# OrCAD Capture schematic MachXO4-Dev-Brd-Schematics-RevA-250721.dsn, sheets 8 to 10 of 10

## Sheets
8 Analog Sense and Control: size B
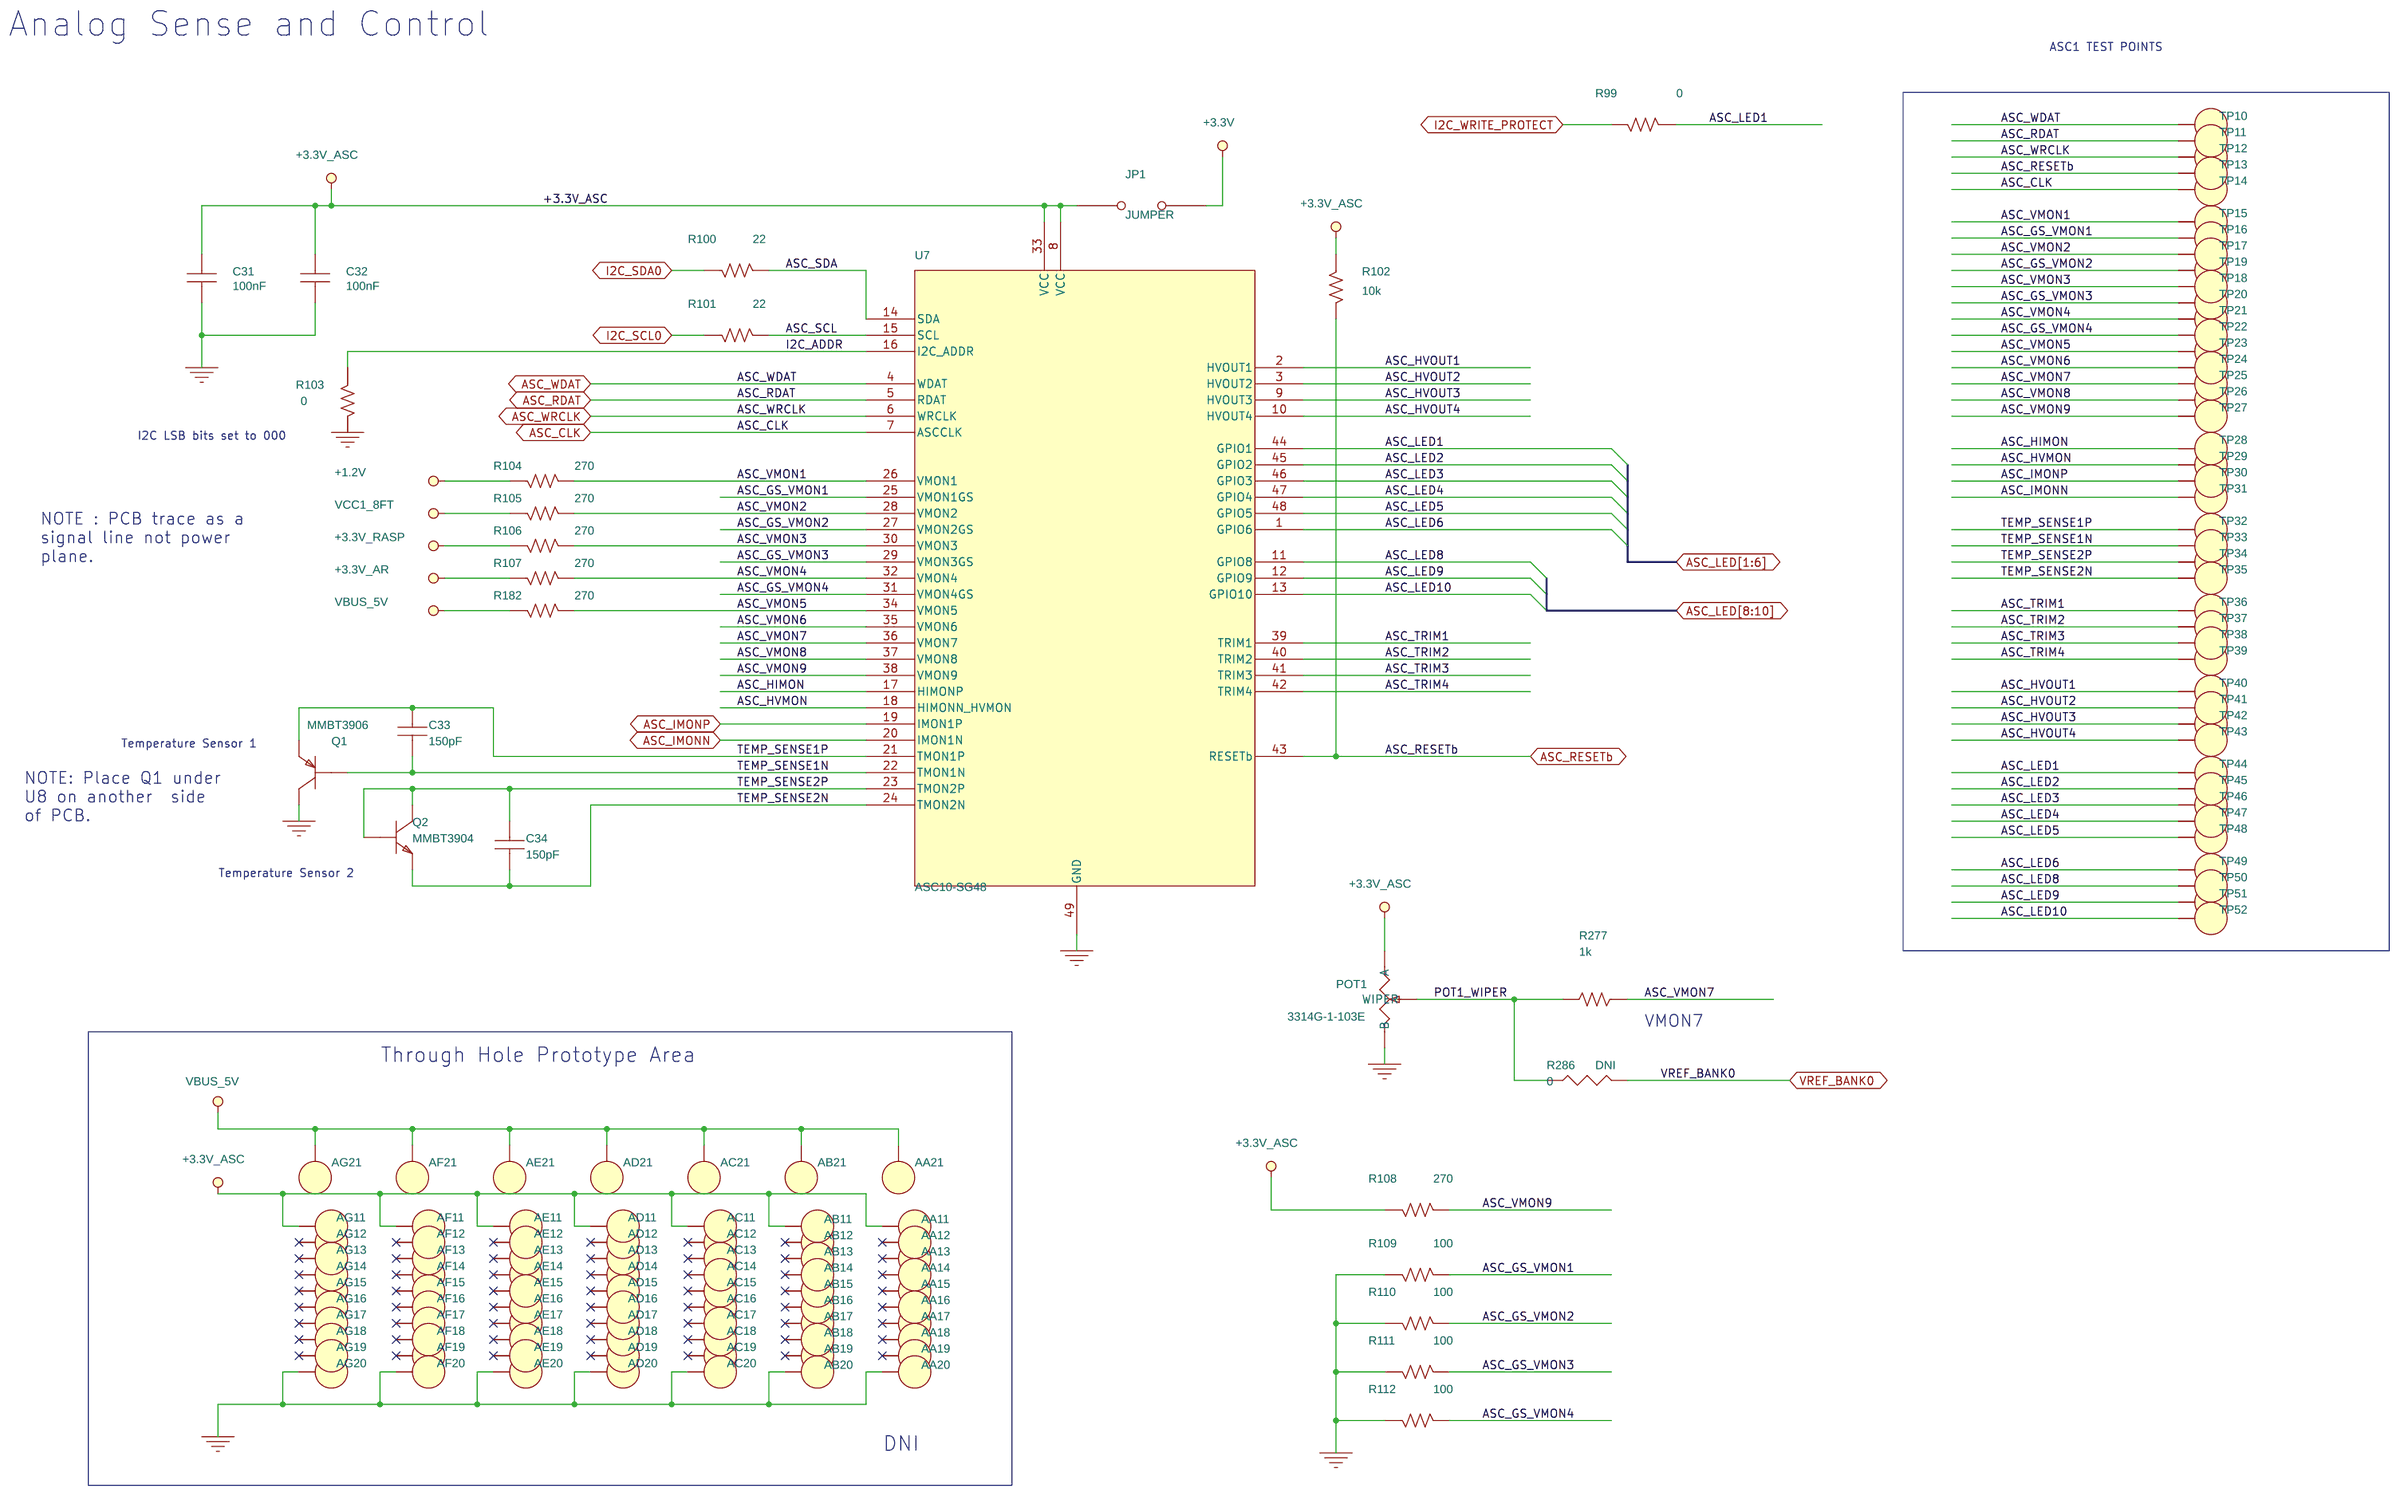
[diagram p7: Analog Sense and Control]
9 POWER DECOUPLING AND LED'S: size B
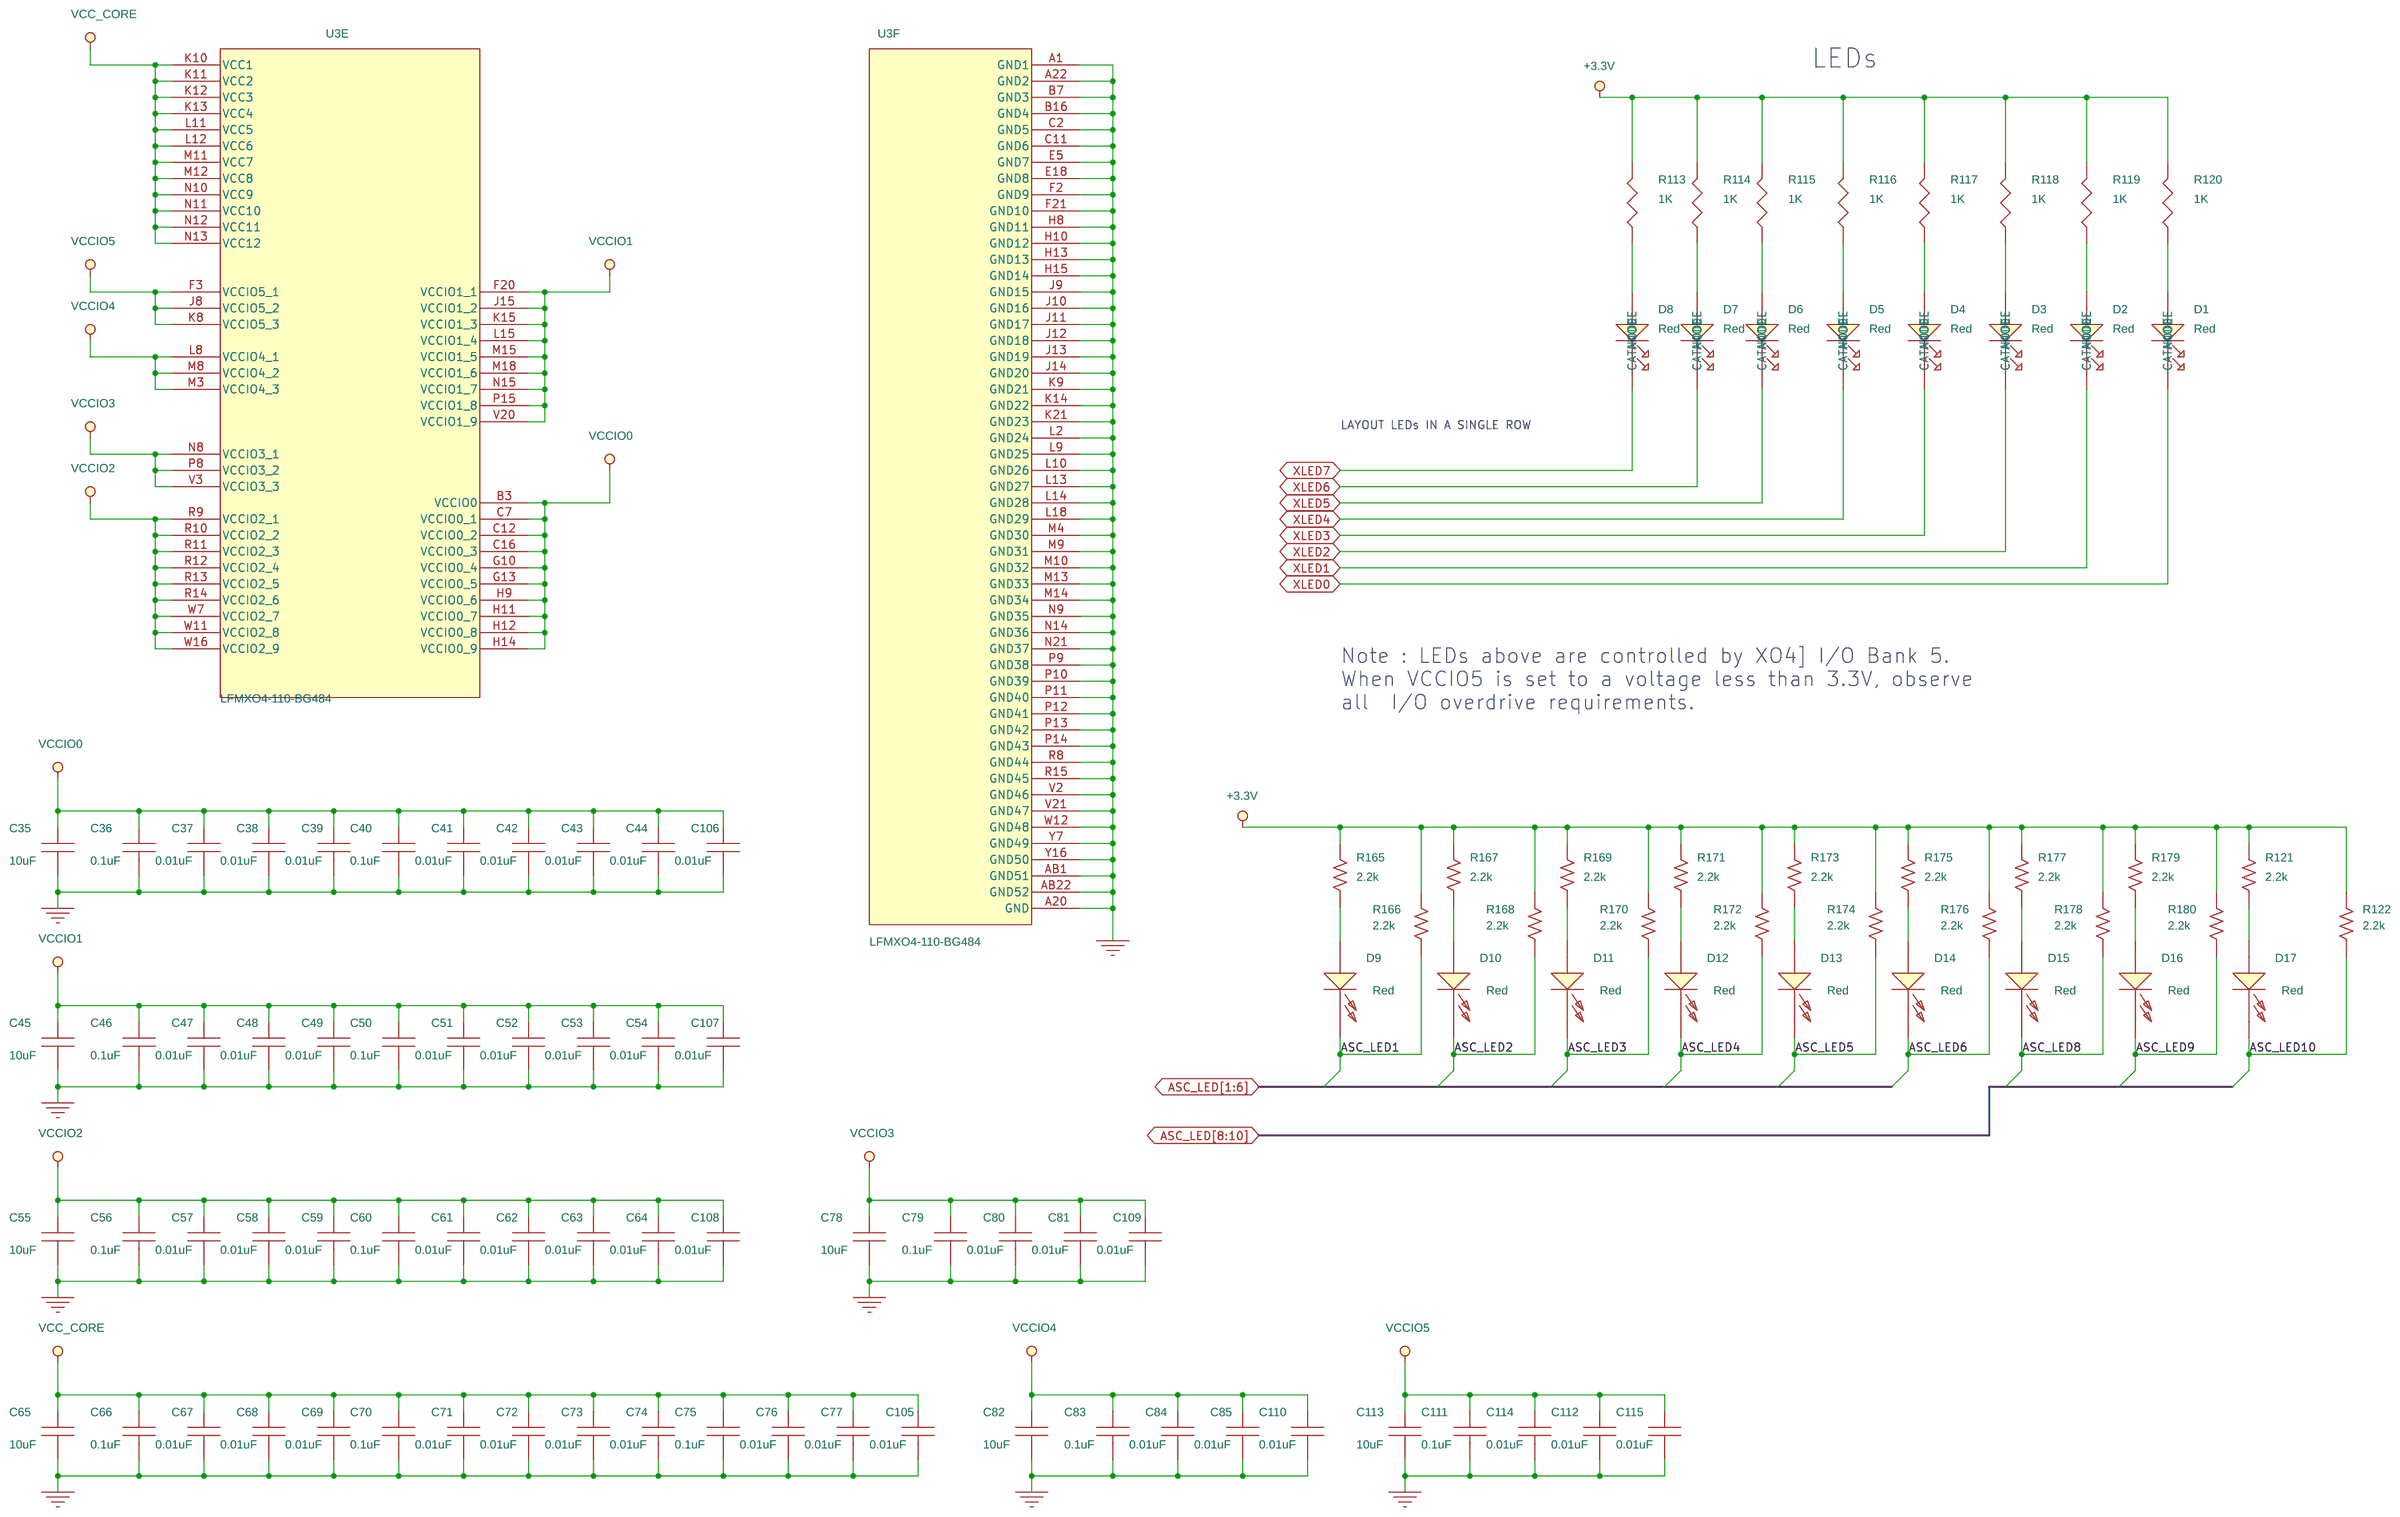
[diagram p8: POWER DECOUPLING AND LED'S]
10 POWER REGULATORS: size B
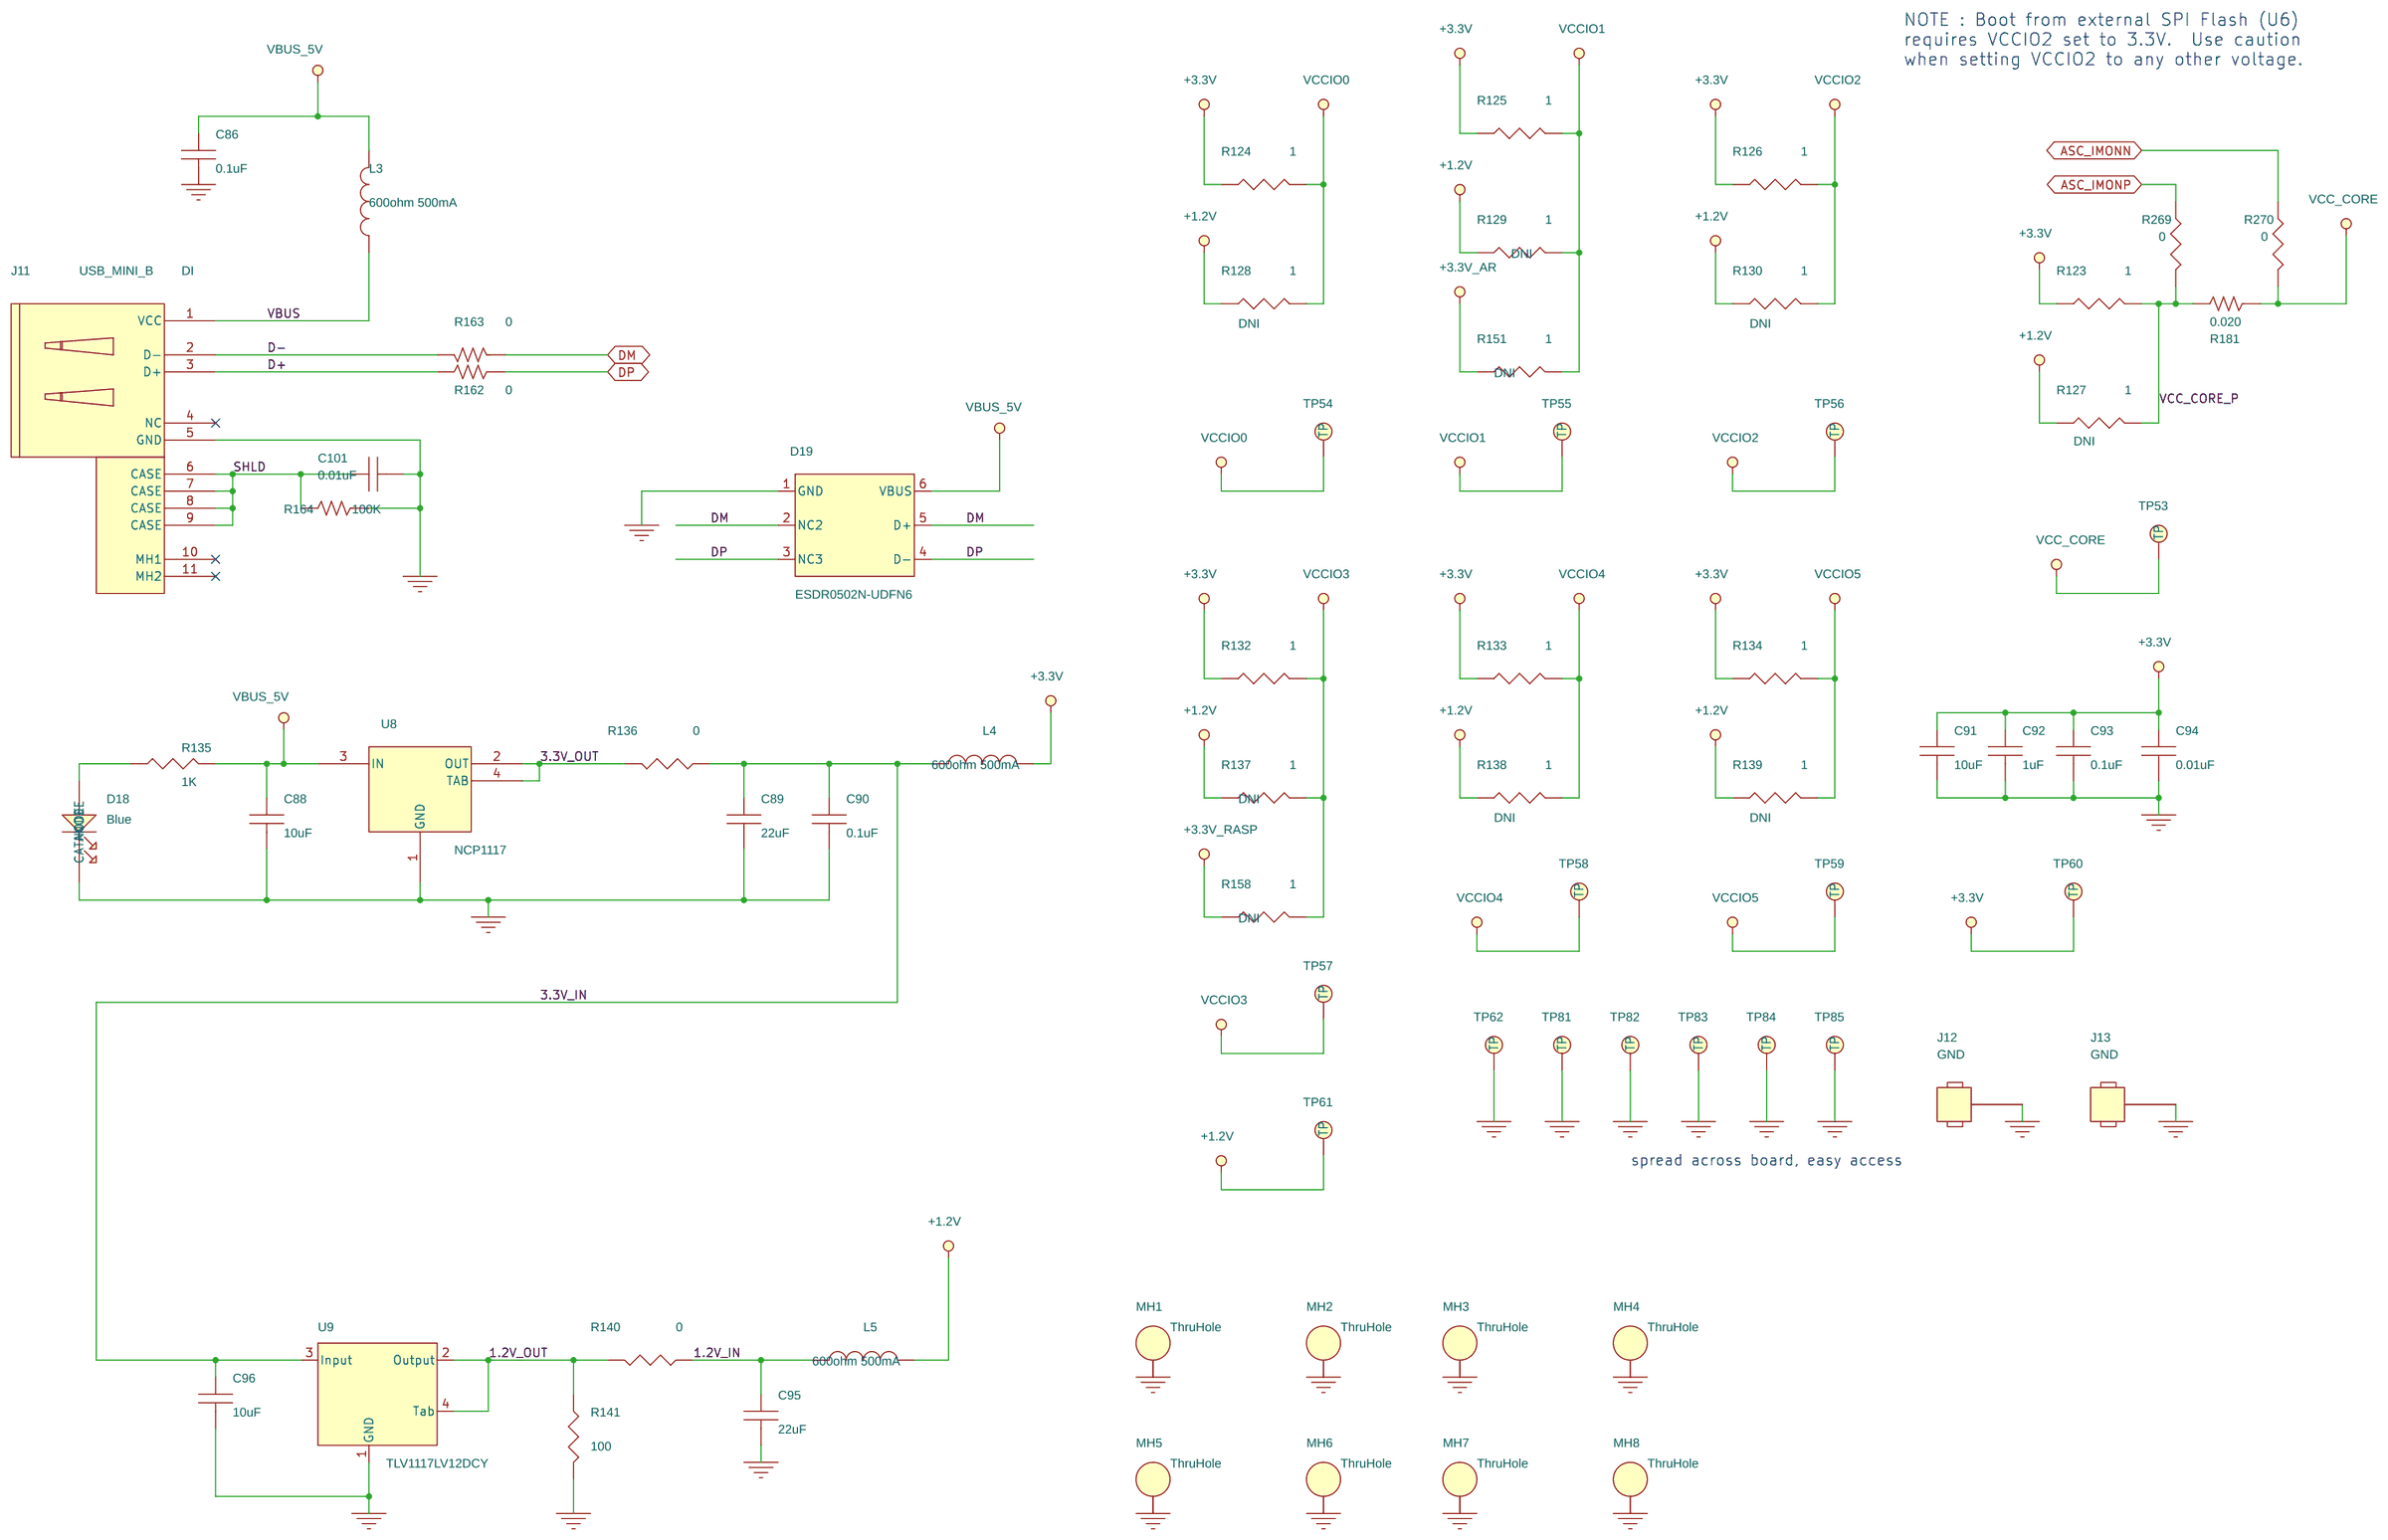
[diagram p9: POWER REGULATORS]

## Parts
sheet Analog Sense and Control
AA11  T POINT R  [TP]
AA12  T POINT R  [TP]
AA13  T POINT R  [TP]
AA14  T POINT R  [TP]
AA15  T POINT R  [TP]
AA16  T POINT R  [TP]
AA17  T POINT R  [TP]
AA18  T POINT R  [TP]
AA19  T POINT R  [TP]
AA20  T POINT R  [TP]
AA21  T POINT R  [TP]
AB11  T POINT R  [TP]
AB12  T POINT R  [TP]
AB13  T POINT R  [TP]
AB14  T POINT R  [TP]
AB15  T POINT R  [TP]
AB16  T POINT R  [TP]
AB17  T POINT R  [TP]
AB18  T POINT R  [TP]
AB19  T POINT R  [TP]
AB20  T POINT R  [TP]
AB21  T POINT R  [TP]
AC11  T POINT R  [TP]
AC12  T POINT R  [TP]
AC13  T POINT R  [TP]
AC14  T POINT R  [TP]
AC15  T POINT R  [TP]
AC16  T POINT R  [TP]
AC17  T POINT R  [TP]
AC18  T POINT R  [TP]
AC19  T POINT R  [TP]
AC20  T POINT R  [TP]
AC21  T POINT R  [TP]
AD11  T POINT R  [TP]
AD12  T POINT R  [TP]
AD13  T POINT R  [TP]
AD14  T POINT R  [TP]
AD15  T POINT R  [TP]
AD16  T POINT R  [TP]
AD17  T POINT R  [TP]
AD18  T POINT R  [TP]
AD19  T POINT R  [TP]
AD20  T POINT R  [TP]
AD21  T POINT R  [TP]
AE11  T POINT R  [TP]
AE12  T POINT R  [TP]
AE13  T POINT R  [TP]
AE14  T POINT R  [TP]
AE15  T POINT R  [TP]
AE16  T POINT R  [TP]
AE17  T POINT R  [TP]
AE18  T POINT R  [TP]
AE19  T POINT R  [TP]
AE20  T POINT R  [TP]
AE21  T POINT R  [TP]
AF11  T POINT R  [TP]
AF12  T POINT R  [TP]
AF13  T POINT R  [TP]
AF14  T POINT R  [TP]
AF15  T POINT R  [TP]
AF16  T POINT R  [TP]
AF17  T POINT R  [TP]
AF18  T POINT R  [TP]
AF19  T POINT R  [TP]
AF20  T POINT R  [TP]
AF21  T POINT R  [TP]
AG11  T POINT R  [TP]
AG12  T POINT R  [TP]
AG13  T POINT R  [TP]
AG14  T POINT R  [TP]
AG15  T POINT R  [TP]
AG16  T POINT R  [TP]
AG17  T POINT R  [TP]
AG18  T POINT R  [TP]
AG19  T POINT R  [TP]
AG20  T POINT R  [TP]
AG21  T POINT R  [TP]
C31  100nF  [C0603]
C32  100nF  [C0603]
C33  150pF  [C0603]
C34  150pF  [C0603]
JP1  JUMPER  [Header_1x2]
POT1  3314G-1-103E  [sot23-3314G-1]
Q1  MMBT3906  [MMBT3906]
Q2  MMBT3904  [MMBT3904]
R99  0  [R0603]
R100  22  [R0603]
R101  22  [R0603]
R102  10k  [R0603]
R103  0  [R0603]
R104  270  [R0603]
R105  270  [R0603]
R106  270  [R0603]
R107  270  [R0603]
R108  270  [R0603]
R109  100  [R0603]
R110  100  [R0603]
R111  100  [R0603]
R112  100  [R0603]
R182  270  [R0603]
R277  1k  [R0603]
R286  0  [R0603]
TP10  T POINT R  [TP]
TP11  T POINT R  [TP]
TP12  T POINT R  [TP]
TP13  T POINT R  [TP]
TP14  T POINT R  [TP]
TP15  T POINT R  [TP]
TP16  T POINT R  [TP]
TP17  T POINT R  [TP]
TP18  T POINT R  [TP]
TP19  T POINT R  [TP]
TP20  T POINT R  [TP]
TP21  T POINT R  [TP]
TP22  T POINT R  [TP]
TP23  T POINT R  [TP]
TP24  T POINT R  [TP]
TP25  T POINT R  [TP]
TP26  T POINT R  [TP]
TP27  T POINT R  [TP]
TP28  T POINT R  [TP]
TP29  T POINT R  [TP]
TP30  T POINT R  [TP]
TP31  T POINT R  [TP]
TP32  T POINT R  [TP]
TP33  T POINT R  [TP]
TP34  T POINT R  [TP]
TP35  T POINT R  [TP]
TP36  T POINT R  [TP]
TP37  T POINT R  [TP]
TP38  T POINT R  [TP]
TP39  T POINT R  [TP]
TP40  T POINT R  [TP]
TP41  T POINT R  [TP]
TP42  T POINT R  [TP]
TP43  T POINT R  [TP]
TP44  T POINT R  [TP]
TP45  T POINT R  [TP]
TP46  T POINT R  [TP]
TP47  T POINT R  [TP]
TP48  T POINT R  [TP]
TP49  T POINT R  [TP]
TP50  T POINT R  [TP]
TP51  T POINT R  [TP]
TP52  T POINT R  [TP]
U7  ASC10-SG48  [TQFN_48]
sheet POWER DECOUPLING AND LED'S
C35  10uF  [C0603]
C36  0.1uF  [C0201]
C37  0.01uF  [C0201]
C38  0.01uF  [C0201]
C39  0.01uF  [C0201]
C40  0.1uF  [C0201]
C41  0.01uF  [C0201]
C42  0.01uF  [C0201]
C43  0.01uF  [C0201]
C44  0.01uF  [C0201]
C45  10uF  [C0603]
C46  0.1uF  [C0201]
C47  0.01uF  [C0201]
C48  0.01uF  [C0201]
C49  0.01uF  [C0201]
C50  0.1uF  [C0201]
C51  0.01uF  [C0201]
C52  0.01uF  [C0201]
C53  0.01uF  [C0201]
C54  0.01uF  [C0201]
C55  10uF  [C0603]
C56  0.1uF  [C0201]
C57  0.01uF  [C0201]
C58  0.01uF  [C0201]
C59  0.01uF  [C0201]
C60  0.1uF  [C0201]
C61  0.01uF  [C0201]
C62  0.01uF  [C0201]
C63  0.01uF  [C0201]
C64  0.01uF  [C0201]
C65  10uF  [C0603]
C66  0.1uF  [C0201]
C67  0.01uF  [C0201]
C68  0.01uF  [C0201]
C69  0.01uF  [C0201]
C70  0.1uF  [C0201]
C71  0.01uF  [C0201]
C72  0.01uF  [C0201]
C73  0.01uF  [C0201]
C74  0.01uF  [C0201]
C75  0.1uF  [C0201]
C76  0.01uF  [C0201]
C77  0.01uF  [C0201]
C78  10uF  [C0603]
C79  0.1uF  [C0201]
C80  0.01uF  [C0201]
C81  0.01uF  [C0201]
C82  10uF  [C0603]
C83  0.1uF  [C0201]
C84  0.01uF  [C0201]
C85  0.01uF  [C0201]
C105  0.01uF  [C0201]
C106  0.01uF  [C0201]
C107  0.01uF  [C0201]
C108  0.01uF  [C0201]
C109  0.01uF  [C0201]
C110  0.01uF  [C0201]
C111  0.1uF  [C0201]
C112  0.01uF  [C0201]
C113  10uF  [C0603]
C114  0.01uF  [C0201]
C115  0.01uF  [C0201]
D1  Red  [led_0603]
D2  Red  [led_0603]
D3  Red  [led_0603]
D4  Red  [led_0603]
D5  Red  [led_0603]
D6  Red  [led_0603]
D7  Red  [led_0603]
D8  Red  [led_0603]
D9  Red  [led_0603]
D10  Red  [led_0603]
D11  Red  [led_0603]
D12  Red  [led_0603]
D13  Red  [led_0603]
D14  Red  [led_0603]
D15  Red  [led_0603]
D16  Red  [led_0603]
D17  Red  [led_0603]
R113  1K  [R0603]
R114  1K  [R0603]
R115  1K  [R0603]
R116  1K  [R0603]
R117  1K  [R0603]
R118  1K  [R0603]
R119  1K  [R0603]
R120  1K  [R0603]
R121  2.2k  [R0603]
R122  2.2k  [R0603]
R165  2.2k  [R0603]
R166  2.2k  [R0603]
R167  2.2k  [R0603]
R168  2.2k  [R0603]
R169  2.2k  [R0603]
R170  2.2k  [R0603]
R171  2.2k  [R0603]
R172  2.2k  [R0603]
R173  2.2k  [R0603]
R174  2.2k  [R0603]
R175  2.2k  [R0603]
R176  2.2k  [R0603]
R177  2.2k  [R0603]
R178  2.2k  [R0603]
R179  2.2k  [R0603]
R180  2.2k  [R0603]
U3  LFMXO4-110-BG484  [BGA484-080]  (sections A,B,C,D,E,F,G)
sheet POWER REGULATORS
C86  0.1uF  [C0402]
C88  10uF  [C0603]
C89  22uF  [cc0805]
C90  0.1uF  [C0402]
C91  10uF  [C0603]
C92  1uF  [C0402]
C93  0.1uF  [C0402]
C94  0.01uF  [C0402]
C95  22uF  [cc0805]
C96  10uF  [C0603]
C101  0.01uF  [C0402]
D18  Blue  [led_0603]
D19  ESDR0502N-UDFN6  [UDFN6_040]
J11  USB_MINI_B  [usb2-0-rec-240-0001-9]
J12  GND  [TUR_TH]
J13  GND  [TUR_TH]
L3  600ohm 500mA  [fb0603]
L4  600ohm 500mA  [fb0603]
L5  600ohm 500mA  [fb0603]
MH1  ThruHole  [MTG125]
MH2  ThruHole  [MTG125]
MH3  ThruHole  [MTG125]
MH4  ThruHole  [MTG125]
MH5  ThruHole  [MTG125]
MH6  ThruHole  [MTG125]
MH7  ThruHole  [MTG125]
MH8  ThruHole  [MTG125]
R123  1  [R0603]
R124  1  [R0603]
R125  1  [R0603]
R126  1  [R0603]
R127  1  [R0603]
R128  1  [R0603]
R129  1  [R0603]
R130  1  [R0603]
R132  1  [R0603]
R133  1  [R0603]
R134  1  [R0603]
R135  1K  [R0603]
R136  0  [R0603]
R137  1  [R0603]
R138  1  [R0603]
R139  1  [R0603]
R140  0  [R0603]
R141  100  [R0603]
R151  1  [R0603]
R158  1  [R0603]
R162  0  [R0402]
R163  0  [R0402]
R164  100K  [R0603]
R181  0.020  [SM_R_1206]
R269  0  [R0603]
R270  0  [R0603]
TP53  TP_S_40_63  [TP]
TP54  TP_S_40_63  [TP]
TP55  TP_S_40_63  [TP]
TP56  TP_S_40_63  [TP]
TP57  TP_S_40_63  [TP]
TP58  TP_S_40_63  [TP]
TP59  TP_S_40_63  [TP]
TP60  TP_S_40_63  [TP]
TP61  TP_S_40_63  [TP]
TP62  TP_S_40_63  [TP]
TP81  TP_S_40_63  [TP]
TP82  TP_S_40_63  [TP]
TP83  TP_S_40_63  [TP]
TP84  TP_S_40_63  [TP]
TP85  TP_S_40_63  [TP]
U8  NCP1117  [sot223_4p]
U9  TLV1117LV12DCY  [sot223_4p]

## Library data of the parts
AA11 AA21 = T_POINT_R_0: Assy: DNI; COMPFIXED: NO; COMPGROUP: 0; COMPHEIGHT: 0.000; COMPKEY: NO; COMPLOC: [100.000,3800.000]; COMPLOCKED: NO; COMPROT: 0; COMPSIDE: TOP; DECOUPLER: NO; MEMORY: NO
AA12 = T_POINT_R_0: Assy: DNI; COMPFIXED: NO; COMPGROUP: 0; COMPHEIGHT: 0.000; COMPKEY: NO; COMPLOC: [100.000,3700.000]; COMPLOCKED: NO; COMPROT: 0; COMPSIDE: TOP; DECOUPLER: NO; MEMORY: NO
AA13 = T_POINT_R_0: Assy: DNI; COMPFIXED: NO; COMPGROUP: 0; COMPHEIGHT: 0.000; COMPKEY: NO; COMPLOC: [100.000,3600.000]; COMPLOCKED: NO; COMPROT: 0; COMPSIDE: TOP; DECOUPLER: NO; MEMORY: NO
AA14 = T_POINT_R_0: Assy: DNI; COMPFIXED: NO; COMPGROUP: 0; COMPHEIGHT: 0.000; COMPKEY: NO; COMPLOC: [100.000,3500.000]; COMPLOCKED: NO; COMPROT: 0; COMPSIDE: TOP; DECOUPLER: NO; MEMORY: NO
AA15 = T_POINT_R_0: Assy: DNI; COMPFIXED: NO; COMPGROUP: 0; COMPHEIGHT: 0.000; COMPKEY: NO; COMPLOC: [100.000,3400.000]; COMPLOCKED: NO; COMPROT: 0; COMPSIDE: TOP; DECOUPLER: NO; MEMORY: NO
AA16 = T_POINT_R_0: Assy: DNI; COMPFIXED: NO; COMPGROUP: 0; COMPHEIGHT: 0.000; COMPKEY: NO; COMPLOC: [100.000,3300.000]; COMPLOCKED: NO; COMPROT: 0; COMPSIDE: TOP; DECOUPLER: NO; MEMORY: NO
AA17 = T_POINT_R_0: Assy: DNI; COMPFIXED: NO; COMPGROUP: 0; COMPHEIGHT: 0.000; COMPKEY: NO; COMPLOC: [100.000,3200.000]; COMPLOCKED: NO; COMPROT: 0; COMPSIDE: TOP; DECOUPLER: NO; MEMORY: NO
AA18 = T_POINT_R_0: Assy: DNI; COMPFIXED: NO; COMPGROUP: 0; COMPHEIGHT: 0.000; COMPKEY: NO; COMPLOC: [100.000,3100.000]; COMPLOCKED: NO; COMPROT: 0; COMPSIDE: TOP; DECOUPLER: NO; MEMORY: NO
AA19 = T_POINT_R_0: Assy: DNI; COMPFIXED: NO; COMPGROUP: 0; COMPHEIGHT: 0.000; COMPKEY: NO; COMPLOC: [100.000,3000.000]; COMPLOCKED: NO; COMPROT: 0; COMPSIDE: TOP; DECOUPLER: NO; MEMORY: NO
AA20 = T_POINT_R_0: Assy: DNI; COMPFIXED: NO; COMPGROUP: 0; COMPHEIGHT: 0.000; COMPKEY: NO; COMPLOC: [100.000,2900.000]; COMPLOCKED: NO; COMPROT: 0; COMPSIDE: TOP; DECOUPLER: NO; MEMORY: NO
AB11 AB21 = T_POINT_R_0: Assy: DNI; COMPFIXED: NO; COMPGROUP: 0; COMPHEIGHT: 0.000; COMPKEY: NO; COMPLOC: [200.000,3800.000]; COMPLOCKED: NO; COMPROT: 0; COMPSIDE: TOP; DECOUPLER: NO; MEMORY: NO
AB12 = T_POINT_R_0: Assy: DNI; COMPFIXED: NO; COMPGROUP: 0; COMPHEIGHT: 0.000; COMPKEY: NO; COMPLOC: [200.000,3700.000]; COMPLOCKED: NO; COMPROT: 0; COMPSIDE: TOP; DECOUPLER: NO; MEMORY: NO
AB13 = T_POINT_R_0: Assy: DNI; COMPFIXED: NO; COMPGROUP: 0; COMPHEIGHT: 0.000; COMPKEY: NO; COMPLOC: [200.000,3600.000]; COMPLOCKED: NO; COMPROT: 0; COMPSIDE: TOP; DECOUPLER: NO; MEMORY: NO
AB14 = T_POINT_R_0: Assy: DNI; COMPFIXED: NO; COMPGROUP: 0; COMPHEIGHT: 0.000; COMPKEY: NO; COMPLOC: [200.000,3500.000]; COMPLOCKED: NO; COMPROT: 0; COMPSIDE: TOP; DECOUPLER: NO; MEMORY: NO
AB15 = T_POINT_R_0: Assy: DNI; COMPFIXED: NO; COMPGROUP: 0; COMPHEIGHT: 0.000; COMPKEY: NO; COMPLOC: [200.000,3400.000]; COMPLOCKED: NO; COMPROT: 0; COMPSIDE: TOP; DECOUPLER: NO; MEMORY: NO
AB16 = T_POINT_R_0: Assy: DNI; COMPFIXED: NO; COMPGROUP: 0; COMPHEIGHT: 0.000; COMPKEY: NO; COMPLOC: [200.000,3300.000]; COMPLOCKED: NO; COMPROT: 0; COMPSIDE: TOP; DECOUPLER: NO; MEMORY: NO
AB17 = T_POINT_R_0: Assy: DNI; COMPFIXED: NO; COMPGROUP: 0; COMPHEIGHT: 0.000; COMPKEY: NO; COMPLOC: [200.000,3200.000]; COMPLOCKED: NO; COMPROT: 0; COMPSIDE: TOP; DECOUPLER: NO; MEMORY: NO
AB18 = T_POINT_R_0: Assy: DNI; COMPFIXED: NO; COMPGROUP: 0; COMPHEIGHT: 0.000; COMPKEY: NO; COMPLOC: [200.000,3100.000]; COMPLOCKED: NO; COMPROT: 0; COMPSIDE: TOP; DECOUPLER: NO; MEMORY: NO
AB19 = T_POINT_R_0: Assy: DNI; COMPFIXED: NO; COMPGROUP: 0; COMPHEIGHT: 0.000; COMPKEY: NO; COMPLOC: [200.000,3000.000]; COMPLOCKED: NO; COMPROT: 0; COMPSIDE: TOP; DECOUPLER: NO; MEMORY: NO
AB20 = T_POINT_R_0: Assy: DNI; COMPFIXED: NO; COMPGROUP: 0; COMPHEIGHT: 0.000; COMPKEY: NO; COMPLOC: [200.000,2900.000]; COMPLOCKED: NO; COMPROT: 0; COMPSIDE: TOP; DECOUPLER: NO; MEMORY: NO
AC11 AC21 = T_POINT_R_0: Assy: DNI; COMPFIXED: NO; COMPGROUP: 0; COMPHEIGHT: 0.000; COMPKEY: NO; COMPLOC: [300.000,3800.000]; COMPLOCKED: NO; COMPROT: 0; COMPSIDE: TOP; DECOUPLER: NO; MEMORY: NO
AC12 = T_POINT_R_0: Assy: DNI; COMPFIXED: NO; COMPGROUP: 0; COMPHEIGHT: 0.000; COMPKEY: NO; COMPLOC: [300.000,3700.000]; COMPLOCKED: NO; COMPROT: 0; COMPSIDE: TOP; DECOUPLER: NO; MEMORY: NO
AC13 = T_POINT_R_0: Assy: DNI; COMPFIXED: NO; COMPGROUP: 0; COMPHEIGHT: 0.000; COMPKEY: NO; COMPLOC: [300.000,3600.000]; COMPLOCKED: NO; COMPROT: 0; COMPSIDE: TOP; DECOUPLER: NO; MEMORY: NO
AC14 = T_POINT_R_0: Assy: DNI; COMPFIXED: NO; COMPGROUP: 0; COMPHEIGHT: 0.000; COMPKEY: NO; COMPLOC: [300.000,3500.000]; COMPLOCKED: NO; COMPROT: 0; COMPSIDE: TOP; DECOUPLER: NO; MEMORY: NO
AC15 = T_POINT_R_0: Assy: DNI; COMPFIXED: NO; COMPGROUP: 0; COMPHEIGHT: 0.000; COMPKEY: NO; COMPLOC: [300.000,3400.000]; COMPLOCKED: NO; COMPROT: 0; COMPSIDE: TOP; DECOUPLER: NO; MEMORY: NO
AC16 = T_POINT_R_0: Assy: DNI; COMPFIXED: NO; COMPGROUP: 0; COMPHEIGHT: 0.000; COMPKEY: NO; COMPLOC: [300.000,3300.000]; COMPLOCKED: NO; COMPROT: 0; COMPSIDE: TOP; DECOUPLER: NO; MEMORY: NO
AC17 = T_POINT_R_0: Assy: DNI; COMPFIXED: NO; COMPGROUP: 0; COMPHEIGHT: 0.000; COMPKEY: NO; COMPLOC: [300.000,3200.000]; COMPLOCKED: NO; COMPROT: 0; COMPSIDE: TOP; DECOUPLER: NO; MEMORY: NO
AC18 = T_POINT_R_0: Assy: DNI; COMPFIXED: NO; COMPGROUP: 0; COMPHEIGHT: 0.000; COMPKEY: NO; COMPLOC: [300.000,3100.000]; COMPLOCKED: NO; COMPROT: 0; COMPSIDE: TOP; DECOUPLER: NO; MEMORY: NO
AC19 = T_POINT_R_0: Assy: DNI; COMPFIXED: NO; COMPGROUP: 0; COMPHEIGHT: 0.000; COMPKEY: NO; COMPLOC: [300.000,3000.000]; COMPLOCKED: NO; COMPROT: 0; COMPSIDE: TOP; DECOUPLER: NO; MEMORY: NO
AC20 = T_POINT_R_0: Assy: DNI; COMPFIXED: NO; COMPGROUP: 0; COMPHEIGHT: 0.000; COMPKEY: NO; COMPLOC: [300.000,2900.000]; COMPLOCKED: NO; COMPROT: 0; COMPSIDE: TOP; DECOUPLER: NO; MEMORY: NO
AD11 AD21 = T_POINT_R_0: Assy: DNI; COMPFIXED: NO; COMPGROUP: 0; COMPHEIGHT: 0.000; COMPKEY: NO; COMPLOC: [400.000,3800.000]; COMPLOCKED: NO; COMPROT: 0; COMPSIDE: TOP; DECOUPLER: NO; MEMORY: NO
AD12 = T_POINT_R_0: Assy: DNI; COMPFIXED: NO; COMPGROUP: 0; COMPHEIGHT: 0.000; COMPKEY: NO; COMPLOC: [400.000,3700.000]; COMPLOCKED: NO; COMPROT: 0; COMPSIDE: TOP; DECOUPLER: NO; MEMORY: NO
AD13 = T_POINT_R_0: Assy: DNI; COMPFIXED: NO; COMPGROUP: 0; COMPHEIGHT: 0.000; COMPKEY: NO; COMPLOC: [400.000,3600.000]; COMPLOCKED: NO; COMPROT: 0; COMPSIDE: TOP; DECOUPLER: NO; MEMORY: NO
AD14 = T_POINT_R_0: Assy: DNI; COMPFIXED: NO; COMPGROUP: 0; COMPHEIGHT: 0.000; COMPKEY: NO; COMPLOC: [400.000,3500.000]; COMPLOCKED: NO; COMPROT: 0; COMPSIDE: TOP; DECOUPLER: NO; MEMORY: NO
AD15 = T_POINT_R_0: Assy: DNI; COMPFIXED: NO; COMPGROUP: 0; COMPHEIGHT: 0.000; COMPKEY: NO; COMPLOC: [400.000,3400.000]; COMPLOCKED: NO; COMPROT: 0; COMPSIDE: TOP; DECOUPLER: NO; MEMORY: NO
AD16 = T_POINT_R_0: Assy: DNI; COMPFIXED: NO; COMPGROUP: 0; COMPHEIGHT: 0.000; COMPKEY: NO; COMPLOC: [400.000,3300.000]; COMPLOCKED: NO; COMPROT: 0; COMPSIDE: TOP; DECOUPLER: NO; MEMORY: NO
AD17 = T_POINT_R_0: Assy: DNI; COMPFIXED: NO; COMPGROUP: 0; COMPHEIGHT: 0.000; COMPKEY: NO; COMPLOC: [400.000,3200.000]; COMPLOCKED: NO; COMPROT: 0; COMPSIDE: TOP; DECOUPLER: NO; MEMORY: NO
AD18 = T_POINT_R_0: Assy: DNI; COMPFIXED: NO; COMPGROUP: 0; COMPHEIGHT: 0.000; COMPKEY: NO; COMPLOC: [400.000,3100.000]; COMPLOCKED: NO; COMPROT: 0; COMPSIDE: TOP; DECOUPLER: NO; MEMORY: NO
AD19 = T_POINT_R_0: Assy: DNI; COMPFIXED: NO; COMPGROUP: 0; COMPHEIGHT: 0.000; COMPKEY: NO; COMPLOC: [400.000,3000.000]; COMPLOCKED: NO; COMPROT: 0; COMPSIDE: TOP; DECOUPLER: NO; MEMORY: NO
AD20 = T_POINT_R_0: Assy: DNI; COMPFIXED: NO; COMPGROUP: 0; COMPHEIGHT: 0.000; COMPKEY: NO; COMPLOC: [400.000,2900.000]; COMPLOCKED: NO; COMPROT: 0; COMPSIDE: TOP; DECOUPLER: NO; MEMORY: NO
AE11 AE21 = T_POINT_R_0: Assy: DNI; COMPFIXED: NO; COMPGROUP: 0; COMPHEIGHT: 0.000; COMPKEY: NO; COMPLOC: [500.000,3800.000]; COMPLOCKED: NO; COMPROT: 0; COMPSIDE: TOP; DECOUPLER: NO; MEMORY: NO
AE12 = T_POINT_R_0: Assy: DNI; COMPFIXED: NO; COMPGROUP: 0; COMPHEIGHT: 0.000; COMPKEY: NO; COMPLOC: [500.000,3700.000]; COMPLOCKED: NO; COMPROT: 0; COMPSIDE: TOP; DECOUPLER: NO; MEMORY: NO
AE13 = T_POINT_R_0: Assy: DNI; COMPFIXED: NO; COMPGROUP: 0; COMPHEIGHT: 0.000; COMPKEY: NO; COMPLOC: [500.000,3600.000]; COMPLOCKED: NO; COMPROT: 0; COMPSIDE: TOP; DECOUPLER: NO; MEMORY: NO
AE14 = T_POINT_R_0: Assy: DNI; COMPFIXED: NO; COMPGROUP: 0; COMPHEIGHT: 0.000; COMPKEY: NO; COMPLOC: [500.000,3500.000]; COMPLOCKED: NO; COMPROT: 0; COMPSIDE: TOP; DECOUPLER: NO; MEMORY: NO
AE15 = T_POINT_R_0: Assy: DNI; COMPFIXED: NO; COMPGROUP: 0; COMPHEIGHT: 0.000; COMPKEY: NO; COMPLOC: [500.000,3400.000]; COMPLOCKED: NO; COMPROT: 0; COMPSIDE: TOP; DECOUPLER: NO; MEMORY: NO
AE16 = T_POINT_R_0: Assy: DNI; COMPFIXED: NO; COMPGROUP: 0; COMPHEIGHT: 0.000; COMPKEY: NO; COMPLOC: [500.000,3300.000]; COMPLOCKED: NO; COMPROT: 0; COMPSIDE: TOP; DECOUPLER: NO; MEMORY: NO
AE17 = T_POINT_R_0: Assy: DNI; COMPFIXED: NO; COMPGROUP: 0; COMPHEIGHT: 0.000; COMPKEY: NO; COMPLOC: [500.000,3200.000]; COMPLOCKED: NO; COMPROT: 0; COMPSIDE: TOP; DECOUPLER: NO; MEMORY: NO
AE18 = T_POINT_R_0: Assy: DNI; COMPFIXED: NO; COMPGROUP: 0; COMPHEIGHT: 0.000; COMPKEY: NO; COMPLOC: [500.000,3100.000]; COMPLOCKED: NO; COMPROT: 0; COMPSIDE: TOP; DECOUPLER: NO; MEMORY: NO
AE19 = T_POINT_R_0: Assy: DNI; COMPFIXED: NO; COMPGROUP: 0; COMPHEIGHT: 0.000; COMPKEY: NO; COMPLOC: [500.000,3000.000]; COMPLOCKED: NO; COMPROT: 0; COMPSIDE: TOP; DECOUPLER: NO; MEMORY: NO
AE20 = T_POINT_R_0: Assy: DNI; COMPFIXED: NO; COMPGROUP: 0; COMPHEIGHT: 0.000; COMPKEY: NO; COMPLOC: [500.000,2900.000]; COMPLOCKED: NO; COMPROT: 0; COMPSIDE: TOP; DECOUPLER: NO; MEMORY: NO
AF11 AF21 = T_POINT_R_0: Assy: DNI; COMPFIXED: NO; COMPGROUP: 0; COMPHEIGHT: 0.000; COMPKEY: NO; COMPLOC: [600.000,3800.000]; COMPLOCKED: NO; COMPROT: 0; COMPSIDE: TOP; DECOUPLER: NO; MEMORY: NO
AF12 = T_POINT_R_0: Assy: DNI; COMPFIXED: NO; COMPGROUP: 0; COMPHEIGHT: 0.000; COMPKEY: NO; COMPLOC: [600.000,3700.000]; COMPLOCKED: NO; COMPROT: 0; COMPSIDE: TOP; DECOUPLER: NO; MEMORY: NO
AF13 = T_POINT_R_0: Assy: DNI; COMPFIXED: NO; COMPGROUP: 0; COMPHEIGHT: 0.000; COMPKEY: NO; COMPLOC: [600.000,3600.000]; COMPLOCKED: NO; COMPROT: 0; COMPSIDE: TOP; DECOUPLER: NO; MEMORY: NO
AF14 = T_POINT_R_0: Assy: DNI; COMPFIXED: NO; COMPGROUP: 0; COMPHEIGHT: 0.000; COMPKEY: NO; COMPLOC: [600.000,3500.000]; COMPLOCKED: NO; COMPROT: 0; COMPSIDE: TOP; DECOUPLER: NO; MEMORY: NO
AF15 = T_POINT_R_0: Assy: DNI; COMPFIXED: NO; COMPGROUP: 0; COMPHEIGHT: 0.000; COMPKEY: NO; COMPLOC: [600.000,3400.000]; COMPLOCKED: NO; COMPROT: 0; COMPSIDE: TOP; DECOUPLER: NO; MEMORY: NO
AF16 = T_POINT_R_0: Assy: DNI; COMPFIXED: NO; COMPGROUP: 0; COMPHEIGHT: 0.000; COMPKEY: NO; COMPLOC: [600.000,3300.000]; COMPLOCKED: NO; COMPROT: 0; COMPSIDE: TOP; DECOUPLER: NO; MEMORY: NO
AF17 = T_POINT_R_0: Assy: DNI; COMPFIXED: NO; COMPGROUP: 0; COMPHEIGHT: 0.000; COMPKEY: NO; COMPLOC: [600.000,3200.000]; COMPLOCKED: NO; COMPROT: 0; COMPSIDE: TOP; DECOUPLER: NO; MEMORY: NO
AF18 = T_POINT_R_0: Assy: DNI; COMPFIXED: NO; COMPGROUP: 0; COMPHEIGHT: 0.000; COMPKEY: NO; COMPLOC: [600.000,3100.000]; COMPLOCKED: NO; COMPROT: 0; COMPSIDE: TOP; DECOUPLER: NO; MEMORY: NO
AF19 = T_POINT_R_0: Assy: DNI; COMPFIXED: NO; COMPGROUP: 0; COMPHEIGHT: 0.000; COMPKEY: NO; COMPLOC: [600.000,3000.000]; COMPLOCKED: NO; COMPROT: 0; COMPSIDE: TOP; DECOUPLER: NO; MEMORY: NO
AF20 = T_POINT_R_0: Assy: DNI; COMPFIXED: NO; COMPGROUP: 0; COMPHEIGHT: 0.000; COMPKEY: NO; COMPLOC: [600.000,2900.000]; COMPLOCKED: NO; COMPROT: 0; COMPSIDE: TOP; DECOUPLER: NO; MEMORY: NO
AG11 = T_POINT_R_0: Assy: DNI; COMPFIXED: NO; COMPGROUP: 0; COMPHEIGHT: 0.000; COMPKEY: NO; COMPLOC: [700.000,3100.000]; COMPLOCKED: NO; COMPROT: 0; COMPSIDE: TOP; DECOUPLER: NO; MEMORY: NO
AG12 = T_POINT_R_0: Assy: DNI; COMPFIXED: NO; COMPGROUP: 0; COMPHEIGHT: 0.000; COMPKEY: NO; COMPLOC: [700.000,3400.000]; COMPLOCKED: NO; COMPROT: 0; COMPSIDE: TOP; DECOUPLER: NO; MEMORY: NO
AG13 = T_POINT_R_0: Assy: DNI; COMPFIXED: NO; COMPGROUP: 0; COMPHEIGHT: 0.000; COMPKEY: NO; COMPLOC: [700.000,3300.000]; COMPLOCKED: NO; COMPROT: 0; COMPSIDE: TOP; DECOUPLER: NO; MEMORY: NO
AG14 = T_POINT_R_0: Assy: DNI; COMPFIXED: NO; COMPGROUP: 0; COMPHEIGHT: 0.000; COMPKEY: NO; COMPLOC: [700.000,3200.000]; COMPLOCKED: NO; COMPROT: 0; COMPSIDE: TOP; DECOUPLER: NO; MEMORY: NO
AG15 = T_POINT_R_0: Assy: DNI; COMPFIXED: NO; COMPGROUP: 0; COMPHEIGHT: 0.000; COMPKEY: NO; COMPLOC: [700.000,3000.000]; COMPLOCKED: NO; COMPROT: 0; COMPSIDE: TOP; DECOUPLER: NO; MEMORY: NO
AG16 = T_POINT_R_0: Assy: DNI; COMPFIXED: NO; COMPGROUP: 0; COMPHEIGHT: 0.000; COMPKEY: NO; COMPLOC: [700.000,2900.000]; COMPLOCKED: NO; COMPROT: 0; COMPSIDE: TOP; DECOUPLER: NO; MEMORY: NO
AG17 AG21 = T_POINT_R_0: Assy: DNI; COMPFIXED: NO; COMPGROUP: 0; COMPHEIGHT: 0.000; COMPKEY: NO; COMPLOC: [700.000,3800.000]; COMPLOCKED: NO; COMPROT: 0; COMPSIDE: TOP; DECOUPLER: NO; MEMORY: NO
AG18 = T_POINT_R_0: Assy: DNI; COMPFIXED: NO; COMPGROUP: 0; COMPHEIGHT: 0.000; COMPKEY: NO; COMPLOC: [700.000,3600.000]; COMPLOCKED: NO; COMPROT: 0; COMPSIDE: TOP; DECOUPLER: NO; MEMORY: NO
AG19 = T_POINT_R_0: Assy: DNI; COMPFIXED: NO; COMPGROUP: 0; COMPHEIGHT: 0.000; COMPKEY: NO; COMPLOC: [700.000,3700.000]; COMPLOCKED: NO; COMPROT: 0; COMPSIDE: TOP; DECOUPLER: NO; MEMORY: NO
AG20 = T_POINT_R_0: Assy: DNI; COMPFIXED: NO; COMPGROUP: 0; COMPHEIGHT: 0.000; COMPKEY: NO; COMPLOC: [700.000,3500.000]; COMPLOCKED: NO; COMPROT: 0; COMPSIDE: TOP; DECOUPLER: NO; MEMORY: NO
C31-C34 = CAP_NP: COMPFIXED: NO; COMPGROUP: 0; COMPHEIGHT: 0.000; COMPKEY: NO; COMPLOC: [2185.000,2685.000]; COMPLOCKED: NO; COMPROT: 90; COMPSIDE: TOP; DECOUPLER: NO; FPLIST: SM/C_0805; MEMORY: NO; populate: DI
JP1 = JUMPER_0
POT1 = POT_SM_2: COMPFIXED: NO; COMPGROUP: 0; COMPHEIGHT: 0.000; COMPKEY: NO; COMPLOC: [2340.000,1325.000]; COMPLOCKED: NO; COMPROT: 90; COMPSIDE: TOP; DECOUPLER: NO; FPLIST: TH/SLIDEPOT/4/25MM; MEMORY: NO; Populate: DI
Q1 = 2N3906_1
Q2 = 2N3904_0
R99 = R: RES 0.0 OHM 1/10W JUMP 0603 SMD; COMPFIXED: NO; COMPHEIGHT: 0.000; COMPKEY: NO; COMPLOC: [3325.000,1400.000]; COMPLOCKED: NO; COMPROT: 180; COMPSIDE: TOP; DECOUPLER: NO; FPLIST: AX/RC05; MEMORY: NO; Populate: DI
R100 R101 R104-R112 R182 = R: COMPFIXED: NO; COMPGROUP: 0; COMPHEIGHT: 0.000; COMPKEY: NO; COMPLOC: [950.000,2200.000]; COMPLOCKED: NO; COMPROT: 0; COMPSIDE: BOT; DECOUPLER: NO; MEMORY: NO; Populate: DI
R102 = R: RES 10K OHM 1/10W 5% 0603; COMPFIXED: NO; COMPGROUP: 0; COMPHEIGHT: 0.000; COMPKEY: NO; COMPLOC: [950.000,2200.000]; COMPLOCKED: NO; COMPROT: 0; COMPSIDE: BOT; DECOUPLER: NO; MEMORY: NO; Populate: DI
R103 = R: RES 0.0 OHM 1/10W JUMP 0603 SMD; COMPFIXED: NO; COMPHEIGHT: 0.000; COMPKEY: NO; COMPLOC: [2340.000,1470.000]; COMPLOCKED: NO; COMPSIDE: BOT; DECOUPLER: NO; MEMORY: NO; Populate: DI
R277 = R: RES 1K OHM 1/10W 1% 0603 SMD; COMPFIXED: NO; COMPGROUP: 0; COMPHEIGHT: 0.000; COMPKEY: NO; COMPLOC: [2340.000,1470.000]; COMPLOCKED: NO; COMPROT: 0; COMPSIDE: BOT; DECOUPLER: NO; MEMORY: NO; Populate: DI
R286 = RES_0: Assy: DNI
TP10-TP52 = T_POINT_R_0: COMPFIXED: NO; COMPGROUP: 0; COMPHEIGHT: 0.000; COMPKEY: NO; COMPLOC: [200.000,3200.000]; COMPLOCKED: NO; COMPROT: 0; COMPSIDE: TOP; DECOUPLER: NO; MEMORY: NO
U7 = ASC1013-48QFN_8
C35 C45 C55 C65 C78 C82 C113 = 10uF_0603
C36 C40 C46 C50 C56 C60 C66 C70 C75 C79 C83 C111 = 0u1_0402: CAP CER 0.1UF 16V 10% X5R 0201; Manufacturer: TDK; Manufacturer Part Number: C0603X5R1C104K030BC
C37-C39 C41-C44 C47-C49 C51-C54 C57-C59 C61-C64 C67-C69 C71-C74 C76 C77 C80 C81 C84 C85 C105-C110 C112 C114 C115 = 0_01uF_0402: CAP CER 10000PF 16V 10% X7R 0201; Manufacturer: Yageo; Manufacturer Part Number: CC0201KRX7R7BB103
D1-D8 = LED_0603_Red
D9 D13 = LN1251C: COMPFIXED: NO; COMPGROUP: 0; COMPHEIGHT: 0.000; COMPKEY: NO; COMPLOC: [2950.000,1925.000]; COMPLOCKED: NO; COMPROT: 0; COMPSIDE: TOP; DECOUPLER: NO; MEMORY: NO
D10 D14 = LN1251C: COMPFIXED: NO; COMPGROUP: 0; COMPHEIGHT: 0.000; COMPKEY: NO; COMPLOC: [2950.000,2000.000]; COMPLOCKED: NO; COMPROT: 0; COMPSIDE: TOP; DECOUPLER: NO; MEMORY: NO
D11 D15 D17 = LN1251C: COMPFIXED: NO; COMPGROUP: 0; COMPHEIGHT: 0.000; COMPKEY: NO; COMPLOC: [2950.000,2075.000]; COMPLOCKED: NO; COMPROT: 0; COMPSIDE: TOP; DECOUPLER: NO; MEMORY: NO
D12 D16 = LN1251C: COMPFIXED: NO; COMPGROUP: 0; COMPHEIGHT: 0.000; COMPKEY: NO; COMPLOC: [2950.000,2150.000]; COMPLOCKED: NO; COMPROT: 0; COMPSIDE: TOP; DECOUPLER: NO; MEMORY: NO
R113-R120 R135 = 1k_0402: RES 1K OHM 1/10W 1% 0603 SMD; Digikey P/N: 311-1.00KHRCT-ND; Manufacturer Part Number: RC0603FR-071KL
R121 R122 R165-R180 = R: COMPFIXED: NO; COMPGROUP: 0; COMPHEIGHT: 0.000; COMPKEY: NO; COMPLOC: [2786.250,4509.367]; COMPLOCKED: NO; COMPROT: 0; COMPSIDE: BOT; DECOUPLER: NO; MEMORY: NO; Populate: DI
U3 = LFMXO4-110-BG484
C86 C90 C93 = 0u1_0402: CAP CER 0.1UF 16V 10% X7R 0402
C88 C91 C96 = 10uF_0603: CAP CER 10UF 10V 20% X5R 0603
C89 C95 = 22uF_0805: CAP CER 22UF 10V 20% X5R 0805
C92 = 1uF_0402: CAP CER 1UF 6.3V 10% X5R 0402
C94 C101 = 0_01uF_0402: CAP CER 10000PF 16V 5% X7R 0402
D18 = LED_0603_Green: LED 468NM BLUE CLEAR 0603 SMD; Digikey P/N: 160-1646-1-ND; Manufacturer Part Number: LTST-C190TBKT
D19 = ESDR0502
J11 = USB_MINI_B_0: COMPFIXED: NO; COMPGROUP: 0; COMPHEIGHT: 0.000; COMPKEY: NO; COMPLOC: [370.000,2590.000]; COMPLOCKED: NO; COMPROT: 270; COMPSIDE: TOP; DECOUPLER: NO; FPLIST: TYPE_B; MEMORY: NO; Populate: DI
J12 J13 = HEADER_1: BOM1_Sensor_Population: POPULATE; BOM2_DUT_Population: DNP; Man. Part #: 1573-2; Manufacturer: Keystone Electronics
L3-L5 = FB0603: FERRITE CHIP 600 OHM 500MA 0603
MH1-MH8 = T_POINT_R_0
R123-R126 R132-R134 = 1R_0.25W_0603: Manufacturer: Vishay
R127-R130 R137-R139 R151 R158 = 1R_0.25W_0603: ASSY: DNI; Manufacturer: Vishay
R136 R140 R269 R270 = 0R_0603: RES 0.0 OHM 1/10W JUMP 0603 SMD
R141 = 100R_0603
R162 R163 = R: COMPFIXED: NO; COMPHEIGHT: 0.000; COMPKEY: NO; COMPLOC: [970.000,1160.000]; COMPLOCKED: NO; COMPROT: 180; COMPSIDE: TOP; DECOUPLER: NO; FPLIST: SM/R_0603; MEMORY: NO; Populate: DI
R164 = R: COMPFIXED: NO; COMPGROUP: 0; COMPHEIGHT: 0.000; COMPKEY: NO; COMPLOC: [970.000,1160.000]; COMPLOCKED: NO; COMPROT: 180; COMPSIDE: TOP; DECOUPLER: NO; FPLIST: SM/R_0603; MEMORY: NO; Populate: DI
R181 = R: COMPFIXED: NO; COMPGROUP: 0; COMPHEIGHT: 0.000; COMPKEY: NO; COMPLOC: [3325.000,1400.000]; COMPLOCKED: NO; COMPROT: 180; COMPSIDE: TOP; DECOUPLER: NO; FPLIST: AX/RC05; MEMORY: NO; Populate: DI
TP53-TP62 TP81-TP85 = TP_S_40_63: Assy: DNI
U8 = NCP1117: IC REG LDO 3.3V 1A SOT223
U9 = FAN1112: IC REG LDO 1.2V 1A SOT223-3; Digikey P/N: 296-28776-1-ND; Manufacturer: TI

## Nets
1.2V_IN: C95.1 L5.2 R140.1
1.2V_OUT: R140.2 R141.1 U9.2(Output) U9.4(Tab)
3.3V_IN: C89.1 C90.1 C96.1 L4.2 R136.1 U9.3(Input)
3.3V_OUT: R136.2 U8.2(OUT) U8.4(TAB)
+1.2V: L5.1 R104.1 R127.1 R128.1 R129.1 R130.1 R137.1 R138.1 R139.1 TP61.1(TP)
+3.3V: C91.1 C92.1 C93.1 C94.1 JP1.1 L4.1 R113.2 R114.2 R115.2 R116.2 R117.2 R118.2 R119.2 R120.2 R121.2 R122.2 R123.1 R124.1 R125.1 R126.1 R132.1 R133.1 R134.1 R165.2 R166.2 R167.2 R168.2 R169.2 R170.2 R171.2 R172.2 R173.2 R174.2 R175.2 R176.2 R177.2 R178.2 R179.2 R180.2 TP60.1(TP) ; also on sheet 3 4 6
+3.3V_AR: R107.1 R151.1 ; also on sheet 5
+3.3V_ASC: AA11.1(TP) AB11.1(TP) AC11.1(TP) AD11.1(TP) AE11.1(TP) AF11.1(TP) AG11.1(TP) C31.1 C32.1 JP1.2 POT1.1(A) R102.1 R108.1 U7.8(VCC) U7.33(VCC)
+3.3V_RASP: R106.1 R158.1 ; also on sheet 7
GND: AA20.1(TP) AB20.1(TP) AC20.1(TP) AD20.1(TP) AE20.1(TP) AF20.1(TP) AG20.1(TP) C31.2 C32.2 C35.2 C36.2 C37.2 C38.2 C39.2 C40.2 C41.2 C42.2 C43.2 C44.2 C45.2 C46.2 C47.2 C48.2 C49.2 C50.2 C51.2 C52.2 C53.2 C54.2 C55.2 C56.2 C57.2 C58.2 C59.2 C60.2 C61.2 C62.2 C63.2 C64.2 C65.2 C66.2 C67.2 C68.2 C69.2 C70.2 C71.2 C72.2 C73.2 C74.2 C75.2 C76.2 C77.2 C78.2 C79.2 C80.2 C81.2 C82.2 C83.2 C84.2 C85.2 C86.2 C88.2 C89.2 C90.2 C91.2 C92.2 C93.2 C94.2 C95.2 C96.2 C101.2 C105.2 C106.2 C107.2 C108.2 C109.2 C110.2 C111.2 C112.2 C113.2 C114.2 C115.2 D18.2(CATHODE) D19.1(GND) J11.5(GND) J12.1 J13.1 MH1.1(TP) MH2.1(TP) MH3.1(TP) MH4.1(TP) MH5.1(TP) MH6.1(TP) MH7.1(TP) MH8.1(TP) POT1.3(B) Q1.3(COLLECTOR) R103.2 R109.1 R110.1 R111.1 R112.1 R141.2 R164.1 TP62.1(TP) TP81.1(TP) TP82.1(TP) TP83.1(TP) TP84.1(TP) TP85.1(TP) U3.A1(GND1) U3.A20(GND) U3.A22(GND2) U3.AB1(GND51) U3.AB22(GND52) U3.B7(GND3) U3.B16(GND4) U3.C2(GND5) U3.C11(GND6) U3.E5(GND7) U3.E18(GND8) U3.F2(GND9) U3.F21(GND10) U3.H8(GND11) U3.H10(GND12) U3.H13(GND13) U3.H15(GND14) U3.J9(GND15) U3.J10(GND16) U3.J11(GND17) U3.J12(GND18) U3.J13(GND19) U3.J14(GND20) U3.K9(GND21) U3.K14(GND22) U3.K21(GND23) U3.L2(GND24) U3.L9(GND25) U3.L10(GND26) U3.L13(GND27) U3.L14(GND28) U3.L18(GND29) U3.M4(GND30) U3.M9(GND31) U3.M10(GND32) U3.M13(GND33) U3.M14(GND34) U3.N9(GND35) U3.N14(GND36) U3.N21(GND37) U3.P9(GND38) U3.P10(GND39) U3.P11(GND40) U3.P12(GND41) U3.P13(GND42) U3.P14(GND43) U3.R8(GND44) U3.R15(GND45) U3.V2(GND46) U3.V21(GND47) U3.W12(GND48) U3.Y7(GND49) U3.Y16(GND50) U7.49(GND) U8.1(GND) U9.1(GND) ; also on sheet 3 4 5 6 7
VBUS: J11.1(VCC) L3.2
VBUS_5V: AA21.1(TP) AB21.1(TP) AC21.1(TP) AD21.1(TP) AE21.1(TP) AF21.1(TP) AG21.1(TP) C86.1 C88.1 D19.6(VBUS) L3.1 R135.2 R182.1 U8.3(IN) ; also on sheet 4 5 6 7
VCC1_8FT: R105.1 ; also on sheet 3 6
VCC_CORE: C65.1 C66.1 C67.1 C68.1 C69.1 C70.1 C71.1 C72.1 C73.1 C74.1 C75.1 C76.1 C77.1 C105.1 R181.1 R270.2 TP53.1(TP) U3.K10(VCC1) U3.K11(VCC2) U3.K12(VCC3) U3.K13(VCC4) U3.L11(VCC5) U3.L12(VCC6) U3.M11(VCC7) U3.M12(VCC8) U3.N10(VCC9) U3.N11(VCC10) U3.N12(VCC11) U3.N13(VCC12)
VCC_CORE_P: R123.2 R127.2 R181.2 R269.2
VCCIO0: C35.1 C36.1 C37.1 C38.1 C39.1 C40.1 C41.1 C42.1 C43.1 C44.1 C106.1 R124.2 R128.2 TP54.1(TP) U3.B3(VCCIO0) U3.C7(VCCIO0_1) U3.C12(VCCIO0_2) U3.C16(VCCIO0_3) U3.G10(VCCIO0_4) U3.G13(VCCIO0_5) U3.H9(VCCIO0_6) U3.H11(VCCIO0_7) U3.H12(VCCIO0_8) U3.H14(VCCIO0_9) ; also on sheet 3 4
VCCIO1: C45.1 C46.1 C47.1 C48.1 C49.1 C50.1 C51.1 C52.1 C53.1 C54.1 C107.1 R125.2 R129.2 R151.2 TP55.1(TP) U3.F20(VCCIO1_1) U3.J15(VCCIO1_2) U3.K15(VCCIO1_3) U3.L15(VCCIO1_4) U3.M15(VCCIO1_5) U3.M18(VCCIO1_6) U3.N15(VCCIO1_7) U3.P15(VCCIO1_8) U3.V20(VCCIO1_9) ; also on sheet 5
VCCIO2: C55.1 C56.1 C57.1 C58.1 C59.1 C60.1 C61.1 C62.1 C63.1 C64.1 C108.1 R126.2 R130.2 TP56.1(TP) U3.R9(VCCIO2_1) U3.R10(VCCIO2_2) U3.R11(VCCIO2_3) U3.R12(VCCIO2_4) U3.R13(VCCIO2_5) U3.R14(VCCIO2_6) U3.W7(VCCIO2_7) U3.W11(VCCIO2_8) U3.W16(VCCIO2_9) ; also on sheet 6
VCCIO3: C78.1 C79.1 C80.1 C81.1 C109.1 R132.2 R137.2 R158.2 TP57.1(TP) U3.N8(VCCIO3_1) U3.P8(VCCIO3_2) U3.V3(VCCIO3_3)
VCCIO4: C82.1 C83.1 C84.1 C85.1 C110.1 R133.2 R138.2 TP58.1(TP) U3.L8(VCCIO4_1) U3.M3(VCCIO4_3) U3.M8(VCCIO4_2)
VCCIO5: C111.1 C112.1 C113.1 C114.1 C115.1 R134.2 R139.2 TP59.1(TP) U3.F3(VCCIO5_1) U3.J8(VCCIO5_2) U3.K8(VCCIO5_3) ; also on sheet 7
ASC_CLK: TP14.1(TP) U7.7(ASCCLK) ; also on sheet 7
ASC_GS_VMON1: R109.2 TP16.1(TP) U7.25(VMON1GS)
ASC_GS_VMON2: R110.2 TP19.1(TP) U7.27(VMON2GS)
ASC_GS_VMON3: R111.2 TP20.1(TP) U7.29(VMON3GS)
ASC_GS_VMON4: R112.2 TP22.1(TP) U7.31(VMON4GS)
ASC_HIMON: TP28.1(TP) U7.17(HIMONP)
ASC_HVMON: TP29.1(TP) U7.18(HIMONN_HVMON)
ASC_HVOUT1: TP40.1(TP) U7.2(HVOUT1)
ASC_HVOUT2: TP41.1(TP) U7.3(HVOUT2)
ASC_HVOUT3: TP42.1(TP) U7.9(HVOUT3)
ASC_HVOUT4: TP43.1(TP) U7.10(HVOUT4)
ASC_IMONN: R270.1 TP31.1(TP) U7.20(IMON1N)
ASC_IMONP: R269.1 TP30.1(TP) U7.19(IMON1P)
ASC_LED1: D9.2(CATHODE) R99.1 R166.1 TP44.1(TP) U7.44(GPIO1)
ASC_LED2: D10.2(CATHODE) R168.1 TP45.1(TP) U7.45(GPIO2)
ASC_LED3: D11.2(CATHODE) R170.1 TP46.1(TP) U7.46(GPIO3)
ASC_LED4: D12.2(CATHODE) R172.1 TP47.1(TP) U7.47(GPIO4)
ASC_LED5: D13.2(CATHODE) R174.1 TP48.1(TP) U7.48(GPIO5)
ASC_LED6: D14.2(CATHODE) R176.1 TP49.1(TP) U7.1(GPIO6)
ASC_LED8: D15.2(CATHODE) R178.1 TP50.1(TP) U7.11(GPIO8)
ASC_LED9: D16.2(CATHODE) R180.1 TP51.1(TP) U7.12(GPIO9)
ASC_LED10: D17.2(CATHODE) R122.1 TP52.1(TP) U7.13(GPIO10)
ASC_RDAT: TP11.1(TP) U7.5(RDAT) ; also on sheet 7
ASC_RESETb: R102.2 TP13.1(TP) U7.43(RESETb) ; also on sheet 4 7
ASC_SCL: R101.2 U7.15(SCL)
ASC_SDA: R100.2 U7.14(SDA)
ASC_TRIM1: TP36.1(TP) U7.39(TRIM1)
ASC_TRIM2: TP37.1(TP) U7.40(TRIM2)
ASC_TRIM3: TP38.1(TP) U7.41(TRIM3)
ASC_TRIM4: TP39.1(TP) U7.42(TRIM4)
ASC_VMON1: R104.2 TP15.1(TP) U7.26(VMON1)
ASC_VMON2: R105.2 TP17.1(TP) U7.28(VMON2)
ASC_VMON3: R106.2 TP18.1(TP) U7.30(VMON3)
ASC_VMON4: R107.2 TP21.1(TP) U7.32(VMON4)
ASC_VMON5: R182.2 TP23.1(TP) U7.34(VMON5)
ASC_VMON6: TP24.1(TP) U7.35(VMON6)
ASC_VMON7: R277.1 TP25.1(TP) U7.36(VMON7)
ASC_VMON8: TP26.1(TP) U7.37(VMON8)
ASC_VMON9: R108.2 TP27.1(TP) U7.38(VMON9)
ASC_WDAT: TP10.1(TP) U7.4(WDAT) ; also on sheet 7
ASC_WRCLK: TP12.1(TP) U7.6(WRCLK) ; also on sheet 7
D+: J11.3(D+) R162.2
D-: J11.2(D-) R163.2
DM: D19.2(NC2) D19.5(D+) R163.1 ; also on sheet 3
DP: D19.3(NC3) D19.4(D-) R162.1 ; also on sheet 3
I2C_ADDR: R103.1 U7.16(I2C_ADDR)
I2C_SCL0: R101.1 ; also on sheet 7
I2C_SDA0: R100.1 ; also on sheet 7
I2C_WRITE_PROTECT: R99.2 ; also on sheet 7
POT1_WIPER: POT1.2(WIPER) R277.2 R286.2
SHLD: C101.1 J11.6(CASE) J11.7(CASE) J11.8(CASE) J11.9(CASE) R164.2
TEMP_SENSE1N: C33.2 Q1.1(BASE) TP33.1(TP) U7.22(TMON1N)
TEMP_SENSE1P: C33.1 Q1.2(EMITTER) TP32.1(TP) U7.21(TMON1P)
TEMP_SENSE2N: C34.2 Q2.2(EMITTER) TP35.1(TP) U7.24(TMON2N)
TEMP_SENSE2P: C34.1 Q2.1(BASE) Q2.3(COLLECTOR) TP34.1(TP) U7.23(TMON2P)
VREF_BANK0: R286.1 ; also on sheet 4
XLED0: D1.2(CATHODE) ; also on sheet 7
XLED1: D2.2(CATHODE) ; also on sheet 7
XLED2: D3.2(CATHODE) ; also on sheet 7
XLED3: D4.2(CATHODE) ; also on sheet 7
XLED4: D5.2(CATHODE) ; also on sheet 7
XLED5: D6.2(CATHODE) ; also on sheet 7
XLED6: D7.2(CATHODE) ; also on sheet 7
XLED7: D8.2(CATHODE) ; also on sheet 7
N16797384: D18.1(ANODE) R135.1
N16949899: D3.1(ANODE) R118.1
N16949903: D1.1(ANODE) R120.1
N16949905: D5.1(ANODE) R116.1
N16949907: D6.1(ANODE) R115.1
N16949915: D2.1(ANODE) R119.1
N16949923: D4.1(ANODE) R117.1
N16949933: D8.1(ANODE) R113.1
N16949951: D7.1(ANODE) R114.1
N16985941: D16.1(ANODE) R179.1
N16985943: D15.1(ANODE) R177.1
N16985945: D14.1(ANODE) R175.1
N16985961: D17.1(ANODE) R121.1
N16986093: D11.1(ANODE) R169.1
N16986095: D10.1(ANODE) R167.1
N16986097: D9.1(ANODE) R165.1
N16986232: D13.1(ANODE) R173.1
N16988001: D12.1(ANODE) R171.1

Not connected (* = marked no-connect by the designer): AA12 1(TP)*; AA13 1(TP)*; AA14 1(TP)*; AA15 1(TP)*; AA16 1(TP)*; AA17 1(TP)*; AA18 1(TP)*; AA19 1(TP)*; AB12 1(TP)*; AB13 1(TP)*; AB14 1(TP)*; AB15 1(TP)*; AB16 1(TP)*; AB17 1(TP)*; AB18 1(TP)*; AB19 1(TP)*; AC12 1(TP)*; AC13 1(TP)*; AC14 1(TP)*; AC15 1(TP)*; AC16 1(TP)*; AC17 1(TP)*; AC18 1(TP)*; AC19 1(TP)*; AD12 1(TP)*; AD13 1(TP)*; AD14 1(TP)*; AD15 1(TP)*; AD16 1(TP)*; AD17 1(TP)*; AD18 1(TP)*; AD19 1(TP)*; AE12 1(TP)*; AE13 1(TP)*; AE14 1(TP)*; AE15 1(TP)*; AE16 1(TP)*; AE17 1(TP)*; AE18 1(TP)*; AE19 1(TP)*; AF12 1(TP)*; AF13 1(TP)*; AF14 1(TP)*; AF15 1(TP)*; AF16 1(TP)*; AF17 1(TP)*; AF18 1(TP)*; AF19 1(TP)*; AG12 1(TP)*; AG13 1(TP)*; AG14 1(TP)*; AG15 1(TP)*; AG16 1(TP)*; AG17 1(TP)*; AG18 1(TP)*; AG19 1(TP)*; J11 4(NC)* 10(MH1)* 11(MH2)*

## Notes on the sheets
sheet 8
- Analog Sense and Control
- ASC1 TEST POINTS
- I2C LSB bits set to 000
- NOTE : PCB trace as a
  signal line not power
  plane.
- Temperature Sensor 1
- NOTE: Place Q1 under
  U8 on another  side
  of PCB.
- Temperature Sensor 2
- VMON7
- Through Hole Prototype Area
- DNI
sheet 9
- LEDs
- LAYOUT LEDs IN A SINGLE ROW
- Note : LEDs above are controlled by XO4] I/O Bank 5.
  When VCCIO5 is set to a voltage less than 3.3V, observe
  all  I/O overdrive requirements.
sheet 10
- NOTE : Boot from external SPI Flash (U6)
  requires VCCIO2 set to 3.3V.  Use caution
  when setting VCCIO2 to any other voltage.
- spread across board, easy access
